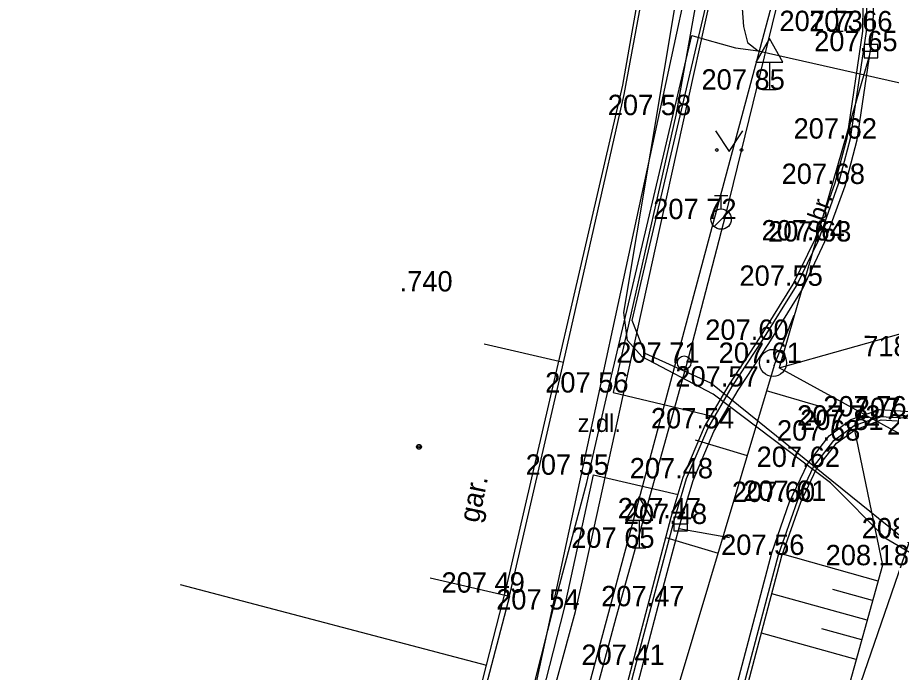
# Model space of a CAD drawing. Extents: x -524633 to -524336, y -1187893 to -1187683.
# Drawn here: x -524615.02 to -524582.86, y -1187753.97 to -1187729.85 of the extents above; entities that cross this region are included whole.
import ezdxf

# ---------------------------------------------------------------- set-up
doc = ezdxf.new("R2010")
doc.units = 0
for name, color, linetype in [('Hranice parcel', 7, 'Continuous'), ('Parcelní čísla', 7, 'Continuous'), ('Vrstva 1', 7, 'Continuous'), ('Vrstva 10', 7, 'Continuous'), ('Vrstva 11', 7, 'Continuous'), ('Vrstva 14', 7, 'Continuous'), ('Vrstva 15', 7, 'Continuous'), ('Vrstva 27', 7, 'Continuous'), ('Vrstva 28', 7, 'Continuous'), ('Vrstva 3', 7, 'Continuous'), ('Vrstva 31', 7, 'Continuous'), ('Vrstva 34', 7, 'Continuous'), ('Vrstva 36', 7, 'Continuous'), ('Vrstva 39', 7, 'Continuous'), ('Vrstva 4', 7, 'Continuous'), ('Vrstva 40', 7, 'Continuous'), ('Vrstva 41', 7, 'Continuous'), ('Vrstva 5', 7, 'Continuous'), ('Vrstva 52', 7, 'Continuous'), ('Vrstva 53', 7, 'Continuous'), ('Vrstva 54', 7, 'Continuous'), ('Vrstva 55', 7, 'Continuous'), ('Vrstva 56', 7, 'Continuous'), ('Vrstva 58', 7, 'Continuous'), ('Vrstva 7', 7, 'Continuous')]:
    doc.layers.add(name, color=color, linetype=linetype)

msp = doc.modelspace()

# ---------------------------------------------------------------- linework, layer by layer
at = {"layer": 'Hranice parcel'}
for p, q in [((-524574.17, -1187725.84), (-524597.74, -1187794.17)), ((-524609.036, -1187750.733), (-524597.76, -1187753.7)), ((-524597.76, -1187753.7), (-524597.03, -1187750.83)), ((-524601.31, -1187767.22), (-524597.76, -1187753.7))]:
    msp.add_line(p, q, dxfattribs=at)
msp.add_lwpolyline([(-524597.03, -1187750.83), (-524592.75, -1187732.34), (-524591.75, -1187726.68)], dxfattribs=at)
at = {"layer": 'Vrstva 1'}
for p, q in [((-524584.89, -1187730.35), (-524584.89, -1187730.35)), ((-524583.78, -1187730.36), (-524583.78, -1187730.36)), ((-524583.61, -1187731.09), (-524583.61, -1187731.09)), ((-524587.353, -1187732.507), (-524587.353, -1187732.507)), ((-524592.7, -1187732.68), (-524592.7, -1187732.68)), ((-524590.801, -1187733.445), (-524590.801, -1187733.445)), ((-524584.37, -1187734.31), (-524584.37, -1187734.31)), ((-524584.81, -1187735.98), (-524584.81, -1187735.98)), ((-524589.129, -1187737.275), (-524589.129, -1187737.275)), ((-524585.55, -1187738.06), (-524585.55, -1187738.06)), ((-524585.31, -1187738.1), (-524585.31, -1187738.1)), ((-524586.36, -1187739.73), (-524586.36, -1187739.73)), ((-524587.59, -1187741.72), (-524587.59, -1187741.72)), ((-524594.93, -1187742.56), (-524594.93, -1187742.56)), ((-524590.49, -1187742.564), (-524590.49, -1187742.564)), ((-524587.22, -1187742.57), (-524587.22, -1187742.57)), ((-524588.72, -1187743.44), (-524588.72, -1187743.44)), ((-524593.104, -1187743.661), (-524593.104, -1187743.661)), ((-524583.26, -1187744.54), (-524583.26, -1187744.54)), ((-524584.24, -1187744.88), (-524584.24, -1187744.88)), ((-524589.62, -1187744.98), (-524589.62, -1187744.98)), ((-524584.22, -1187745.04), (-524584.22, -1187745.04)), ((-524584.98, -1187745.43), (-524584.98, -1187745.43)), ((-524585.73, -1187746.4), (-524585.73, -1187746.4)), ((-524593.822, -1187746.688), (-524593.822, -1187746.688)), ((-524590.4, -1187746.82), (-524590.4, -1187746.82)), ((-524586.61, -1187747.69), (-524586.61, -1187747.69)), ((-524586.32, -1187747.65), (-524586.32, -1187747.65)), ((-524590.84, -1187748.29), (-524590.84, -1187748.29)), ((-524590.62, -1187748.5), (-524590.62, -1187748.5)), ((-524592.147, -1187749.379), (-524592.147, -1187749.379)), ((-524592.07, -1187749.24), (-524592.07, -1187749.24)), ((-524587.02, -1187749.64), (-524587.02, -1187749.64)), ((-524583.19, -1187750.02), (-524583.19, -1187750.02)), ((-524596.96, -1187751.02), (-524596.96, -1187751.02)), ((-524596.92, -1187751.03), (-524596.92, -1187751.03)), ((-524596.92, -1187751.16), (-524596.92, -1187751.16)), ((-524591.45, -1187751.53), (-524591.45, -1187751.53)), ((-524594.909, -1187751.652), (-524594.909, -1187751.652)), ((-524592.27, -1187753.69), (-524592.27, -1187753.69))]:
    msp.add_line(p, q, dxfattribs=at)
at = {"layer": 'Vrstva 10'}
for points in [[(-524609.859, -1187798.22), (-524609.439, -1187797.69), (-524606.939, -1187794.18), (-524604.669, -1187790.88), (-524603.03, -1187788.23), (-524600.449, -1187783.54), (-524598.719, -1187780.05), (-524597.999, -1187778.04), (-524597.319, -1187775.53), (-524596.759, -1187772.72), (-524596.06, -1187768.17), (-524594.249, -1187761.26), (-524592.27, -1187753.69), (-524590.839, -1187748.29), (-524590.399, -1187746.82), (-524589.619, -1187744.98), (-524588.719, -1187743.44), (-524587.589, -1187741.72), (-524586.359, -1187739.73), (-524585.549, -1187738.06), (-524584.809, -1187735.98), (-524584.369, -1187734.31), (-524583.78, -1187730.36), (-524583.77, -1187729.36)], [(-524592.359, -1187770.71), (-524591.919, -1187768.17), (-524589.43, -1187758.74), (-524587.02, -1187749.64), (-524586.32, -1187747.65), (-524585.73, -1187746.4), (-524584.98, -1187745.43), (-524584.239, -1187744.88), (-524583.26, -1187744.54), (-524582.21, -1187744.6), (-524580.91, -1187745.21), (-524580.64, -1187745.45), (-524579.819, -1187746.2), (-524578.919, -1187746.98), (-524577.67, -1187747.9), (-524576.719, -1187748.34), (-524576.29, -1187748.66)]]:
    msp.add_lwpolyline(points, dxfattribs=at)
at = {"layer": 'Vrstva 11'}
for p, q in [((-524589.713, -1187727.336), (-524590.801, -1187733.445)), ((-524590.801, -1187733.445), (-524593.104, -1187743.661)), ((-524593.104, -1187743.661), (-524589.497, -1187744.513)), ((-524594.909, -1187751.652), (-524593.822, -1187746.688)), ((-524593.822, -1187746.688), (-524590.714, -1187747.419)), ((-524597.482, -1187761.661), (-524594.909, -1187751.652))]:
    msp.add_line(p, q, dxfattribs=at)
for points in [[(-524594.375, -1187761.227), (-524592.396, -1187753.657), (-524590.964, -1187748.255), (-524590.522, -1187746.776), (-524589.736, -1187744.922), (-524588.83, -1187743.371), (-524587.699, -1187741.65), (-524586.473, -1187739.667), (-524585.669, -1187738.01), (-524584.934, -1187735.942), (-524584.497, -1187734.284), (-524583.91, -1187730.35), (-524583.9, -1187729.375), (-524584.143, -1187728.37), (-524584.836, -1187726.658), (-524585.328, -1187725.832), (-524586.018, -1187724.906), (-524586.943, -1187723.991), (-524588.194, -1187723.153), (-524589.123, -1187722.713), (-524592.731, -1187721.816)], [(-524609.439, -1187797.69), (-524609.239, -1187797.84), (-524606.734, -1187794.323), (-524604.46, -1187791.017), (-524602.814, -1187788.356), (-524600.228, -1187783.656), (-524598.489, -1187780.148), (-524597.761, -1187778.115), (-524597.076, -1187775.587), (-524596.513, -1187772.763), (-524595.815, -1187768.221), (-524594.007, -1187761.323), (-524591.45, -1187751.53), (-524590.599, -1187748.358), (-524590.164, -1187746.905), (-524589.395, -1187745.092), (-524588.507, -1187743.572), (-524587.378, -1187741.854), (-524586.14, -1187739.851), (-524585.309, -1187738.1), (-524584.57, -1187736.054), (-524584.124, -1187734.36), (-524583.53, -1187730.38), (-524583.519, -1187729.331)], [(-524592.606, -1187770.667), (-524592.164, -1187768.117), (-524589.672, -1187758.676), (-524587.259, -1187749.566), (-524586.609, -1187747.69), (-524585.944, -1187746.269), (-524585.157, -1187745.25), (-524584.357, -1187744.656), (-524583.295, -1187744.288), (-524582.148, -1187744.353), (-524580.699, -1187745.03), (-524579.653, -1187746.013), (-524578.763, -1187746.785), (-524577.542, -1187747.684), (-524576.59, -1187748.124), (-524576.12, -1187748.46), (-524576.29, -1187748.66)], [(-524592.23, -1187770.719), (-524591.792, -1187768.198), (-524589.304, -1187758.773), (-524586.896, -1187749.678), (-524586.2, -1187747.699), (-524585.618, -1187746.468), (-524584.888, -1187745.524), (-524584.22, -1187745.04), (-524583.241, -1187744.671), (-524582.242, -1187744.728), (-524580.982, -1187745.32), (-524580.727, -1187745.547), (-524579.906, -1187746.297), (-524579, -1187747.082), (-524577.736, -1187748.012), (-524576.786, -1187748.452), (-524576.379, -1187748.755)]]:
    msp.add_lwpolyline(points, dxfattribs=at)
at = {"layer": 'Vrstva 14'}
msp.add_lwpolyline([(-524584.22, -1187745.04), (-524583.189, -1187750.02), (-524585.969, -1187759.98), (-524588.419, -1187763.52), (-524589.719, -1187770.64), (-524588.19, -1187773.68), (-524586.909, -1187777.13)], dxfattribs=at)
at = {"layer": 'Vrstva 15'}
for p, q in [((-524583.352, -1187750.602), (-524586.875, -1187749.618)), ((-524583.553, -1187751.324), (-524585.019, -1187750.915)), ((-524583.755, -1187752.046), (-524587.263, -1187751.067)), ((-524584.158, -1187753.491), (-524587.648, -1187752.517)), ((-524583.956, -1187752.769), (-524585.422, -1187752.36))]:
    msp.add_line(p, q, dxfattribs=at)
at = {"layer": 'Vrstva 27'}
for p, q in [((-524583.86, -1187731.09), (-524583.36, -1187731.09)), ((-524590.869, -1187748.5), (-524590.369, -1187748.5))]:
    msp.add_line(p, q, dxfattribs=at)
for points in [[(-524583.86, -1187731.34), (-524583.36, -1187731.34), (-524583.36, -1187730.84), (-524583.86, -1187730.84)], [(-524590.869, -1187748.75), (-524590.369, -1187748.75), (-524590.369, -1187748.25), (-524590.869, -1187748.25)]]:
    msp.add_lwpolyline(points, close=True, dxfattribs=at)
msp.add_circle((-524587.22, -1187742.57), 0.5, dxfattribs=at)
at = {"layer": 'Vrstva 28'}
for p, q in [((-524589.379, -1187736.4), (-524588.879, -1187736.4)), ((-524589.129, -1187736.9), (-524589.129, -1187736.4)), ((-524589.387, -1187737.547), (-524588.857, -1187737.017))]:
    msp.add_line(p, q, dxfattribs=at)
msp.add_circle((-524589.129, -1187737.275), 0.375, dxfattribs=at)
at = {"layer": 'Vrstva 31'}
msp.add_circle((-524590.49, -1187742.564), 0.25, dxfattribs=at)
at = {"layer": 'Vrstva 34'}
for p, q in [((-524584.889, -1187729.332), (-524584.889, -1187730.35)), ((-524585.139, -1187730.35), (-524584.639, -1187730.35)), ((-524587.353, -1187731.489), (-524587.353, -1187732.507)), ((-524587.603, -1187732.507), (-524587.103, -1187732.507)), ((-524592.147, -1187748.361), (-524592.147, -1187749.379)), ((-524592.397, -1187749.379), (-524591.897, -1187749.379))]:
    msp.add_line(p, q, dxfattribs=at)
for points in [[(-524587.853, -1187731.489), (-524586.853, -1187731.489), (-524587.353, -1187730.623)], [(-524592.647, -1187748.361), (-524591.647, -1187748.361), (-524592.147, -1187747.495)]]:
    msp.add_lwpolyline(points, close=True, dxfattribs=at)
at = {"layer": 'Vrstva 36'}
msp.add_lwpolyline([(-524589.333, -1187734.029), (-524588.833, -1187734.779), (-524588.333, -1187734.029)], dxfattribs=at)
for centre in [(-524589.283, -1187734.729), (-524588.384, -1187734.729)]:
    msp.add_circle(centre, 0.05, dxfattribs=at)
at = {"layer": 'Vrstva 39'}
for radius in [0.09, 0.0398]:
    msp.add_circle((-524600.248, -1187745.659), radius, dxfattribs=at)
at = {"layer": 'Vrstva 5'}
for p, q in [((-524592.7, -1187732.68), (-524591.63, -1187726.94)), ((-524594.93, -1187742.56), (-524592.7, -1187732.68)), ((-524594.93, -1187742.56), (-524597.853, -1187741.884)), ((-524596.92, -1187751.16), (-524594.93, -1187742.56)), ((-524599.843, -1187750.484), (-524596.92, -1187751.16))]:
    msp.add_line(p, q, dxfattribs=at)
at = {"layer": 'Vrstva 52'}
for points in [[(-524604.888, -1187810.358), (-524606.68, -1187809.553), (-524607.041, -1187809.142), (-524606.651, -1187808.01), (-524604.828, -1187805.241), (-524602.389, -1187802.751), (-524595.518, -1187792.842), (-524592.363, -1187786.571), (-524587.685, -1187773.341), (-524584.851, -1187764.936), (-524580.85, -1187751.486), (-524581.943, -1187749.433), (-524589.511, -1187743.31), (-524591.925, -1187742.225), (-524592.398, -1187741.002), (-524589.2, -1187727.331), (-524588.107, -1187723.138), (-524586.572, -1187712.872)], [(-524607.441, -1187809.976), (-524607.53, -1187809.669), (-524606.817, -1187807.941), (-524600.734, -1187800.222), (-524596.921, -1187794.77), (-524594.569, -1187790.848), (-524590.203, -1187780.476), (-524585.928, -1187767.436), (-524582.597, -1187756.424), (-524580.946, -1187751.47), (-524581.141, -1187750.169), (-524583.06, -1187749.051), (-524585.106, -1187746.981), (-524589.425, -1187743.717), (-524592.03, -1187742.347), (-524592.569, -1187741.747), (-524592.712, -1187740.711), (-524590.247, -1187725.964), (-524590.389, -1187724.462)]]:
    msp.add_lwpolyline(points, dxfattribs=at)
at = {"layer": 'Vrstva 53'}
msp.add_line((-524591.54, -1187738.348), (-524588.325, -1187723.697), dxfattribs=at)
for points in [[(-524589.366, -1187726.746), (-524589.049, -1187726.945), (-524588.464, -1187728.018), (-524588.301, -1187730.182), (-524588.164, -1187730.769), (-524587.767, -1187731.073)], [(-524604.005, -1187785.146), (-524602.35, -1187779.473), (-524599.769, -1187768.881), (-524597.508, -1187760.218), (-524597.936, -1187759.989), (-524597.786, -1187759.147), (-524597.19, -1187759.061), (-524595.268, -1187751.506), (-524594.067, -1187746.974), (-524593.215, -1187743.258), (-524590.207, -1187730.512), (-524589.661, -1187730.676), (-524588.596, -1187730.961), (-524587.767, -1187731.073)], [(-524587.767, -1187731.073), (-524573.147, -1187734.381), (-524571.979, -1187734.744), (-524570.56, -1187735.142), (-524562.878, -1187736.596), (-524552.81, -1187739.087), (-524548.867, -1187739.789), (-524546.782, -1187740.936), (-524543.928, -1187741.628), (-524541.406, -1187742.844), (-524531.308, -1187745.219), (-524528.991, -1187745.215), (-524527.551, -1187745.165), (-524527.006, -1187745.511)], [(-524620.431, -1187810.083), (-524611.699, -1187798.589), (-524604.954, -1187789.128), (-524602.104, -1187779.718), (-524594.484, -1187751.724), (-524594.226, -1187750.59), (-524591.54, -1187738.348)]]:
    msp.add_lwpolyline(points, dxfattribs=at)
at = {"layer": 'Vrstva 54'}
msp.add_line((-524602.824, -1187787.351), (-524586.61, -1187726.932), dxfattribs=at)
at = {"layer": 'Vrstva 55'}
for p, q in [((-524583.68, -1187731.27), (-524586.99, -1187742.75)), ((-524586.99, -1187742.75), (-524577.6, -1187740.1)), ((-524587.179, -1187742.67), (-524586.441, -1187740.811)), ((-524587.179, -1187742.67), (-524604.019, -1187798.98)), ((-524575.98, -1187748.81), (-524586.99, -1187742.75)), ((-524585.539, -1187744.167), (-524587.456, -1187743.594)), ((-524590.085, -1187745.406), (-524588.169, -1187745.979)), ((-524590.69, -1187748.67), (-524588.825, -1187748.998)), ((-524591.16, -1187748.999), (-524589.243, -1187749.572))]:
    msp.add_line(p, q, dxfattribs=at)
at = {"layer": 'Vrstva 56'}
msp.add_lwpolyline([(-524586.54, -1187727.18), (-524588.97, -1187737.12), (-524590.36, -1187742.45), (-524593, -1187751.96), (-524600.51, -1187779.94), (-524604.9, -1187791.29), (-524607.89, -1187795.49), (-524608.098, -1187795.783), (-524608.38, -1187796.18), (-524608.59, -1187796.44), (-524610.16, -1187798.34), (-524617.66, -1187808), (-524619.897, -1187810.877)], dxfattribs=at)
at = {"layer": 'Vrstva 58'}
msp.add_lwpolyline([(-524606.424, -1187788.222), (-524597.11, -1187759.84), (-524589.35, -1187723.88)], dxfattribs=at)
at = {"layer": 'Vrstva 7'}
msp.add_line((-524596.92, -1187751.16), (-524604.21, -1187779.08), dxfattribs=at)

# ---------------------------------------------------------------- texts
at = {"layer": 'Parcelní čísla'}
msp.add_text('.740', height=0.75, dxfattribs=at).set_placement((-524600.963, -1187739.938))
msp.add_text('7185/8', height=0.75, rotation=359.7121, dxfattribs=at).set_placement((-524583.902, -1187742.321))
at = {"layer": 'Vrstva 3'}
for s, p in [('207.62', (-524586.464, -1187734.31)), ('207 72 ', (-524591.629, -1187737.275)), ('207.55', (-524588.455, -1187739.73)), ('207.57', (-524590.814, -1187743.44)), ('207.76', (-524585.371, -1187744.54)), ('207.62', (-524587.824, -1187746.4)), ('207.47', (-524592.934, -1187748.29)), ('208.15', (-524583.955, -1187749.03)), ('207.56', (-524589.131, -1187749.64)), ('207.41', (-524594.27, -1187753.69))]:
    msp.add_text(s, height=0.75, dxfattribs=at).set_placement(p)
at = {"layer": 'Vrstva 4'}
for s, p in [('207.73', (-524586.984, -1187730.35)), ('207.66', (-524585.891, -1187730.36)), ('207.65', (-524585.705, -1187731.09)), ('207 85 ', (-524589.853, -1187732.507)), ('207 58 ', (-524593.301, -1187733.445)), ('207.68', (-524586.904, -1187735.98)), ('207.64', (-524587.644, -1187738.06)), ('207.63', (-524587.404, -1187738.1)), ('207.60', (-524589.714, -1187741.72)), ('207 71 ', (-524592.99, -1187742.564)), ('207.61', (-524589.22, -1187742.57)), ('207 56 ', (-524595.604, -1187743.661)), ('207.81', (-524584.21, -1187744.6)), ('207.54', (-524591.714, -1187744.98)), ('207.72', (-524586.334, -1187744.88)), ('207.81', (-524586.22, -1187745.04)), ('207.86', (-524583.021, -1187745.21)), ('207.68', (-524587.074, -1187745.43)), ('207 55 ', (-524596.322, -1187746.688)), ('207.48', (-524592.494, -1187746.82)), ('207.60', (-524588.734, -1187747.69)), ('207.61', (-524588.32, -1187747.65)), ('207.48', (-524592.714, -1187748.5)), ('207 65 ', (-524594.647, -1187749.379)), ('208.18', (-524585.284, -1187750.02)), ('207 49 ', (-524599.42, -1187751.03)), ('207 54 ', (-524597.409, -1187751.652)), ('207.47', (-524593.544, -1187751.53))]:
    msp.add_text(s, height=0.75, dxfattribs=at).set_placement(p)
at = {"layer": 'Vrstva 40'}
msp.add_text('obr.', height=0.65, rotation=70.416, dxfattribs=at).set_placement((-524585.513, -1187737.854))
msp.add_text('z.dl.', height=0.65, dxfattribs=at).set_placement((-524594.41, -1187745.112))
at = {"layer": 'Vrstva 41'}
msp.add_text('gar.', height=0.75, rotation=78.1638, dxfattribs=at).set_placement((-524598.057, -1187748.485))

doc.saveas('drawing.dxf')
